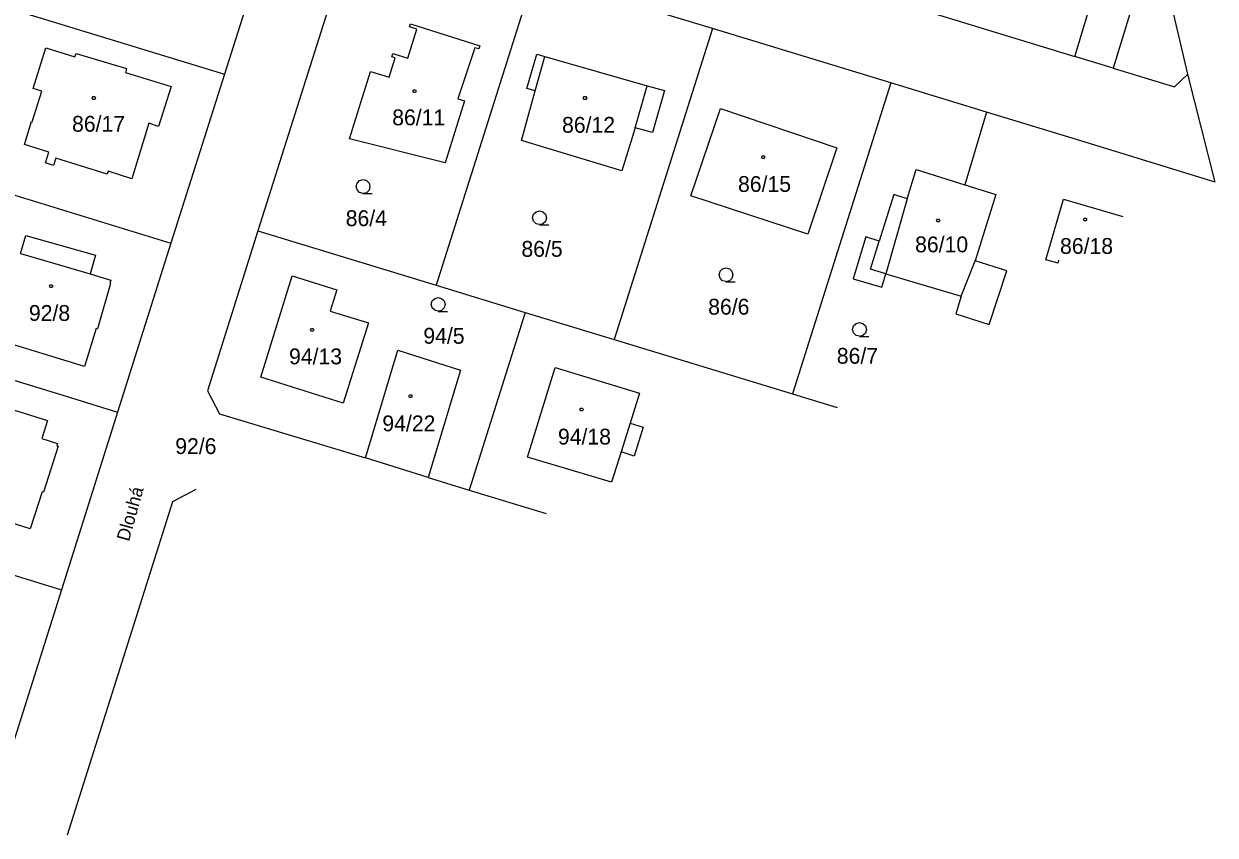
# Model space of a CAD drawing. Extents: x -759060 to -757386, y -1172273 to -1170948.
# Drawn here: x -758007.6 to -757879.8, y -1171577.8 to -1171490.7 of the extents above; entities that cross this region are included whole.
import ezdxf

# ---------------------------------------------------------------- set-up
doc = ezdxf.new("R2010")
doc.units = 0
for name, color, linetype in [('Vrstva 1', 7, 'Continuous'), ('Vrstva 12', 7, 'Continuous'), ('Vrstva 2', 7, 'Continuous'), ('Vrstva 3', 7, 'Continuous'), ('Vrstva 4', 7, 'Continuous'), ('Vrstva 5', 7, 'Continuous'), ('Vrstva 7', 7, 'Continuous')]:
    doc.layers.add(name, color=color, linetype=linetype)

msp = doc.modelspace()

# ---------------------------------------------------------------- linework, layer by layer
at = {"layer": 'Vrstva 1'}
for p, q in [((-757882.7, -1171496.11), (-757887.69, -1171474.68)), ((-757980.65, -1171478.97), (-757986.07, -1171496.14)), ((-757972.53, -1171481.45), (-757982.47, -1171512.93)), ((-757887.51, -1171484.91), (-757890.7, -1171495.49)), ((-758019.54, -1171485.89), (-757986.07, -1171496.14)), ((-757952.81, -1171485.38), (-757963.35, -1171518.77)), ((-757933.7, -1171491.22), (-757952.81, -1171485.38)), ((-757910.62, -1171489.39), (-757894.84, -1171494.23)), ((-757966.4, -1171494.42), (-757965.42, -1171491.31)), ((-757966.21, -1171491.06), (-757966.1, -1171490.73)), ((-757965.42, -1171491.31), (-757966.21, -1171491.06)), ((-757966.1, -1171490.73), (-757958.66, -1171493.08)), ((-757933.7, -1171491.22), (-757944.24, -1171524.61)), ((-757914.58, -1171497.06), (-757933.7, -1171491.22)), ((-758006.58, -1171497.65), (-758005.22, -1171493.31)), ((-758005.22, -1171493.31), (-758002.1, -1171494.28)), ((-758002.1, -1171494.28), (-758001.98, -1171493.9)), ((-758001.98, -1171493.9), (-757996.58, -1171495.53)), ((-757968.1, -1171494.25), (-757968, -1171493.92)), ((-757968, -1171493.92), (-757966.4, -1171494.42)), ((-757959.2, -1171493.28), (-757961.01, -1171498.78)), ((-757958.77, -1171493.41), (-757959.2, -1171493.28)), ((-757958.66, -1171493.08), (-757958.77, -1171493.41)), ((-757953.63, -1171497.65), (-757952.55, -1171493.98)), ((-757952.55, -1171493.98), (-757951.7, -1171494.22)), ((-757968.4, -1171496.45), (-757967.75, -1171494.37)), ((-757967.75, -1171494.37), (-757968.1, -1171494.25)), ((-757951.7, -1171494.22), (-757940.7, -1171497.36)), ((-757890.7, -1171495.49), (-757894.84, -1171494.23)), ((-757996.58, -1171495.53), (-757996.67, -1171495.95)), ((-757996.67, -1171495.95), (-757991.79, -1171497.43)), ((-757986.07, -1171496.14), (-757991.8, -1171514.26)), ((-757972.66, -1171503.06), (-757970.38, -1171495.82)), ((-757970.38, -1171495.82), (-757968.4, -1171496.45)), ((-757890.7, -1171495.49), (-757884.15, -1171497.48)), ((-757884.15, -1171497.48), (-757882.7, -1171496.11)), ((-757879.77, -1171507.7), (-757882.7, -1171496.11)), ((-758005.66, -1171497.93), (-758006.58, -1171497.65)), ((-757991.79, -1171497.43), (-757993.13, -1171501.73)), ((-757952.73, -1171497.91), (-757953.63, -1171497.65)), ((-757940.7, -1171497.36), (-757938.85, -1171497.87)), ((-757914.58, -1171497.06), (-757925.12, -1171530.44)), ((-757904.31, -1171500.2), (-757914.58, -1171497.06)), ((-758006.68, -1171501.25), (-758005.66, -1171497.93)), ((-757960.3, -1171499), (-757962.4, -1171505.65)), ((-757961.01, -1171498.78), (-757960.3, -1171499)), ((-757954.21, -1171503.23), (-757952.73, -1171497.91)), ((-757938.85, -1171497.87), (-757940.14, -1171502.4)), ((-757936.02, -1171509.18), (-757932.86, -1171499.82)), ((-757932.86, -1171499.82), (-757920.37, -1171504.02)), ((-757904.31, -1171500.2), (-757906.64, -1171508)), ((-757895.47, -1171502.9), (-757904.31, -1171500.2)), ((-758007.53, -1171503.67), (-758006.78, -1171501.22)), ((-758006.78, -1171501.22), (-758006.68, -1171501.25)), ((-757994.18, -1171501.38), (-757995.99, -1171507.34)), ((-757993.13, -1171501.73), (-757994.18, -1171501.38)), ((-757942, -1171501.88), (-757943.44, -1171506.49)), ((-757940.14, -1171502.4), (-757942, -1171501.88)), ((-757879.77, -1171507.7), (-757895.47, -1171502.9)), ((-757895.47, -1171502.9), (-757895.47, -1171502.9)), ((-758025.27, -1171504), (-757991.8, -1171514.26)), ((-758004.91, -1171504.5), (-758007.53, -1171503.67)), ((-757962.4, -1171505.65), (-757972.66, -1171503.06)), ((-757943.44, -1171506.49), (-757954.21, -1171503.23)), ((-757920.37, -1171504.02), (-757923.48, -1171513.28)), ((-758005.27, -1171505.65), (-758004.91, -1171504.5)), ((-758004.14, -1171505.13), (-758004.39, -1171505.91)), ((-757998.66, -1171506.87), (-758004.14, -1171505.13)), ((-758004.39, -1171505.91), (-758005.27, -1171505.65)), ((-757998.55, -1171506.52), (-757998.66, -1171506.87)), ((-757995.99, -1171507.34), (-757998.55, -1171506.52)), ((-757912.83, -1171509.49), (-757911.86, -1171506.37)), ((-757911.86, -1171506.37), (-757906.64, -1171508)), ((-757906.64, -1171508), (-757903.3, -1171509.04)), ((-757879.77, -1171507.7), (-757879.77, -1171507.7)), ((-757923.48, -1171513.28), (-757936.02, -1171509.18)), ((-757914.25, -1171509.05), (-757915.81, -1171514.04)), ((-757912.83, -1171509.49), (-757914.25, -1171509.05)), ((-757903.3, -1171509.04), (-757905.52, -1171516.16)), ((-757897.93, -1171516.03), (-757896.06, -1171509.54)), ((-757896.06, -1171509.54), (-757889.67, -1171511.38)), ((-757889.67, -1171511.38), (-757889.67, -1171511.38)), ((-757982.47, -1171512.93), (-757987.89, -1171530.09)), ((-757982.47, -1171512.93), (-757963.35, -1171518.77)), ((-758007.94, -1171515.36), (-758007.36, -1171513.45)), ((-758007.36, -1171513.45), (-757999.9, -1171515.56)), ((-757991.8, -1171514.26), (-757997.52, -1171532.38)), ((-757917.25, -1171513.59), (-757918.6, -1171518.07)), ((-757915.81, -1171514.04), (-757917.25, -1171513.59)), ((-757999.9, -1171515.56), (-758000.48, -1171517.55)), ((-757902.13, -1171517.22), (-757905.52, -1171516.16)), ((-757896.63, -1171516.4), (-757897.93, -1171516.03)), ((-757896.63, -1171516.4), (-757896.54, -1171516.1)), ((-757896.63, -1171516.4), (-757896.63, -1171516.4)), ((-757896.54, -1171516.1), (-757896.54, -1171516.1)), ((-758000.48, -1171517.55), (-757998.26, -1171518.22)), ((-757998.26, -1171518.22), (-757998.37, -1171518.56)), ((-757982.17, -1171528.65), (-757978.79, -1171517.77)), ((-757978.79, -1171517.77), (-757974.01, -1171519.26)), ((-757918.6, -1171518.07), (-757915.55, -1171518.99)), ((-757915.55, -1171518.99), (-757915.12, -1171517.54)), ((-757915.12, -1171517.54), (-757911.24, -1171518.7)), ((-757904.02, -1171523), (-757902.13, -1171517.22)), ((-757998.28, -1171518.59), (-757999.68, -1171523.45)), ((-757998.37, -1171518.56), (-757998.28, -1171518.59)), ((-757974.01, -1171519.26), (-757974.72, -1171521.54)), ((-757963.35, -1171518.77), (-757953.8, -1171521.69)), ((-757911.24, -1171518.7), (-757911.24, -1171518.7)), ((-757911.24, -1171518.7), (-757907.02, -1171519.95)), ((-757907.02, -1171519.95), (-757907.58, -1171521.84)), ((-758030.99, -1171522.11), (-758003.04, -1171530.69)), ((-757974.72, -1171521.54), (-757970.62, -1171522.82)), ((-757953.8, -1171521.69), (-757959.8, -1171540.76)), ((-757953.8, -1171521.69), (-757944.24, -1171524.61)), ((-757907.58, -1171521.84), (-757904.02, -1171523)), ((-757970.62, -1171522.82), (-757973.32, -1171531.42)), ((-758001.07, -1171527.49), (-758010.74, -1171524.52)), ((-757999.83, -1171523.4), (-758001.07, -1171527.49)), ((-757999.68, -1171523.45), (-757999.83, -1171523.4)), ((-757944.24, -1171524.61), (-757925.12, -1171530.44)), ((-757970.94, -1171537.3), (-757967.47, -1171525.74)), ((-757967.47, -1171525.74), (-757960.74, -1171527.89)), ((-757960.74, -1171527.89), (-757964.21, -1171539.39)), ((-757953.55, -1171537.21), (-757950.59, -1171527.59)), ((-757950.59, -1171527.59), (-757941.55, -1171530.37)), ((-757973.32, -1171531.42), (-757982.17, -1171528.65)), ((-758012.95, -1171530.82), (-758005.04, -1171533.3)), ((-758003.04, -1171530.69), (-757997.52, -1171532.38)), ((-757987.89, -1171530.09), (-757986.58, -1171532.58)), ((-757941.55, -1171530.37), (-757942.55, -1171533.56)), ((-757925.12, -1171530.44), (-757920.34, -1171531.9)), ((-757920.34, -1171531.9), (-757920.34, -1171531.9)), ((-757920.34, -1171531.9), (-757920.34, -1171531.9)), ((-758005.04, -1171533.3), (-758005.64, -1171535.21)), ((-757997.52, -1171532.38), (-758003.55, -1171551.46)), ((-757986.58, -1171532.58), (-757970.94, -1171537.3)), ((-757942.55, -1171533.56), (-757941.15, -1171534)), ((-757941.15, -1171534), (-757942.1, -1171537.1)), ((-758005.64, -1171535.21), (-758003.96, -1171535.74)), ((-758003.92, -1171536.05), (-758005.49, -1171540.97)), ((-758003.96, -1171535.74), (-758004.05, -1171536.01)), ((-758004.05, -1171536.01), (-758003.92, -1171536.05)), ((-757964.21, -1171539.39), (-757970.94, -1171537.3)), ((-757944.52, -1171539.89), (-757953.55, -1171537.21)), ((-757943.51, -1171536.65), (-757944.52, -1171539.89)), ((-757942.1, -1171537.1), (-757943.51, -1171536.65)), ((-757964.21, -1171539.39), (-757959.8, -1171540.76)), ((-758005.63, -1171540.93), (-758006.9, -1171544.93)), ((-758005.49, -1171540.97), (-758005.63, -1171540.93)), ((-757989.14, -1171540.69), (-757991.65, -1171542.02)), ((-757989.14, -1171540.69), (-757989.14, -1171540.69)), ((-757959.8, -1171540.76), (-757951.55, -1171543.28)), ((-758006.9, -1171544.93), (-758016.47, -1171541.87)), ((-757991.65, -1171542.02), (-758002.95, -1171577.79)), ((-758028.41, -1171543.82), (-758003.55, -1171551.46)), ((-757951.55, -1171543.28), (-757951.55, -1171543.28)), ((-757951.55, -1171543.28), (-757951.55, -1171543.28)), ((-758003.55, -1171551.46), (-758011.08, -1171575.3)), ((-758002.95, -1171577.79), (-758002.95, -1171577.79))]:
    msp.add_line(p, q, dxfattribs=at)
at = {"layer": 'Vrstva 12'}
for p, q in [((-757887.51, -1171484.91), (-757890.7, -1171495.49)), ((-757894.84, -1171494.23), (-757893.33, -1171489.26)), ((-757966.4, -1171494.42), (-757965.42, -1171491.31)), ((-757966.21, -1171491.06), (-757966.1, -1171490.73)), ((-757965.42, -1171491.31), (-757966.21, -1171491.06)), ((-757966.1, -1171490.73), (-757958.66, -1171493.08)), ((-758006.58, -1171497.65), (-758005.22, -1171493.31)), ((-758005.22, -1171493.31), (-758002.1, -1171494.28)), ((-758002.1, -1171494.28), (-758001.98, -1171493.9)), ((-758001.98, -1171493.9), (-757996.58, -1171495.53)), ((-757968.1, -1171494.25), (-757968, -1171493.92)), ((-757968, -1171493.92), (-757966.4, -1171494.42)), ((-757959.2, -1171493.28), (-757961.01, -1171498.78)), ((-757958.77, -1171493.41), (-757959.2, -1171493.28)), ((-757958.66, -1171493.08), (-757958.77, -1171493.41)), ((-757968.4, -1171496.45), (-757967.75, -1171494.37)), ((-757967.75, -1171494.37), (-757968.1, -1171494.25)), ((-757952.73, -1171497.91), (-757951.7, -1171494.22)), ((-757951.7, -1171494.22), (-757940.7, -1171497.36)), ((-757890.7, -1171495.49), (-757894.84, -1171494.23)), ((-757996.58, -1171495.53), (-757996.67, -1171495.95)), ((-757996.67, -1171495.95), (-757991.79, -1171497.43)), ((-757972.66, -1171503.06), (-757970.38, -1171495.82)), ((-757970.38, -1171495.82), (-757968.4, -1171496.45)), ((-758005.66, -1171497.93), (-758006.58, -1171497.65)), ((-757991.79, -1171497.43), (-757993.13, -1171501.73)), ((-757942, -1171501.88), (-757940.7, -1171497.36)), ((-758006.68, -1171501.25), (-758005.66, -1171497.93)), ((-757960.3, -1171499), (-757962.4, -1171505.65)), ((-757961.01, -1171498.78), (-757960.3, -1171499)), ((-757954.21, -1171503.23), (-757952.73, -1171497.91)), ((-757936.02, -1171509.18), (-757932.86, -1171499.82)), ((-757932.86, -1171499.82), (-757920.37, -1171504.02)), ((-758007.53, -1171503.67), (-758006.78, -1171501.22)), ((-758006.78, -1171501.22), (-758006.68, -1171501.25)), ((-757994.18, -1171501.38), (-757995.99, -1171507.34)), ((-757993.13, -1171501.73), (-757994.18, -1171501.38)), ((-757942, -1171501.88), (-757943.44, -1171506.49)), ((-758004.91, -1171504.5), (-758007.53, -1171503.67)), ((-757962.4, -1171505.65), (-757972.66, -1171503.06)), ((-757943.44, -1171506.49), (-757954.21, -1171503.23)), ((-757920.37, -1171504.02), (-757923.48, -1171513.28)), ((-758005.27, -1171505.65), (-758004.91, -1171504.5)), ((-758004.14, -1171505.13), (-758004.39, -1171505.91)), ((-757998.66, -1171506.87), (-758004.14, -1171505.13)), ((-758004.39, -1171505.91), (-758005.27, -1171505.65)), ((-757998.55, -1171506.52), (-757998.66, -1171506.87)), ((-757995.99, -1171507.34), (-757998.55, -1171506.52)), ((-757912.83, -1171509.49), (-757911.86, -1171506.37)), ((-757911.86, -1171506.37), (-757906.64, -1171508)), ((-757906.64, -1171508), (-757903.3, -1171509.04)), ((-757923.48, -1171513.28), (-757936.02, -1171509.18)), ((-757903.3, -1171509.04), (-757905.52, -1171516.16)), ((-757912.83, -1171509.49), (-757915.12, -1171517.54)), ((-757897.93, -1171516.03), (-757896.06, -1171509.54)), ((-757896.06, -1171509.54), (-757889.67, -1171511.38)), ((-757889.67, -1171511.38), (-757889.67, -1171511.38)), ((-758007.94, -1171515.36), (-758000.48, -1171517.55)), ((-757907.02, -1171519.95), (-757905.52, -1171516.16)), ((-757896.63, -1171516.4), (-757897.93, -1171516.03)), ((-757896.63, -1171516.4), (-757896.54, -1171516.1)), ((-757896.63, -1171516.4), (-757896.54, -1171516.1)), ((-757896.63, -1171516.4), (-757896.63, -1171516.4)), ((-757896.54, -1171516.1), (-757896.54, -1171516.1)), ((-757896.54, -1171516.1), (-757896.54, -1171516.1)), ((-758000.48, -1171517.55), (-757998.26, -1171518.22)), ((-757998.26, -1171518.22), (-757998.37, -1171518.56)), ((-757982.17, -1171528.65), (-757978.79, -1171517.77)), ((-757978.79, -1171517.77), (-757974.01, -1171519.26)), ((-757915.12, -1171517.54), (-757911.24, -1171518.7)), ((-757998.28, -1171518.59), (-757999.68, -1171523.45)), ((-757998.37, -1171518.56), (-757998.28, -1171518.59)), ((-757974.01, -1171519.26), (-757974.72, -1171521.54)), ((-757911.24, -1171518.7), (-757907.02, -1171519.95)), ((-757974.72, -1171521.54), (-757970.62, -1171522.82)), ((-757970.62, -1171522.82), (-757973.32, -1171531.42)), ((-758001.07, -1171527.49), (-758010.74, -1171524.52)), ((-757999.83, -1171523.4), (-758001.07, -1171527.49)), ((-757999.68, -1171523.45), (-757999.83, -1171523.4)), ((-757970.94, -1171537.3), (-757967.47, -1171525.74)), ((-757967.47, -1171525.74), (-757960.74, -1171527.89)), ((-757960.74, -1171527.89), (-757964.21, -1171539.39)), ((-757953.55, -1171537.21), (-757950.59, -1171527.59)), ((-757950.59, -1171527.59), (-757941.55, -1171530.37)), ((-757973.32, -1171531.42), (-757982.17, -1171528.65)), ((-758012.95, -1171530.82), (-758005.04, -1171533.3)), ((-757941.55, -1171530.37), (-757942.55, -1171533.56)), ((-758005.04, -1171533.3), (-758005.64, -1171535.21)), ((-757942.55, -1171533.56), (-757943.51, -1171536.65)), ((-758005.64, -1171535.21), (-758003.96, -1171535.74)), ((-758003.92, -1171536.05), (-758005.49, -1171540.97)), ((-758003.96, -1171535.74), (-758004.05, -1171536.01)), ((-758004.05, -1171536.01), (-758003.92, -1171536.05)), ((-757964.21, -1171539.39), (-757970.94, -1171537.3)), ((-757944.52, -1171539.89), (-757953.55, -1171537.21)), ((-757943.51, -1171536.65), (-757944.52, -1171539.89)), ((-758005.63, -1171540.93), (-758006.9, -1171544.93)), ((-758005.49, -1171540.97), (-758005.63, -1171540.93)), ((-758006.9, -1171544.93), (-758016.47, -1171541.87))]:
    msp.add_line(p, q, dxfattribs=at)
at = {"layer": 'Vrstva 3'}
for points in [[(-757971.18, -1171508.92), (-757971.56, -1171508.82), (-757971.83, -1171508.55), (-757971.93, -1171508.18), (-757971.83, -1171507.81), (-757971.56, -1171507.54), (-757971.19, -1171507.44), (-757970.82, -1171507.54), (-757970.55, -1171507.81), (-757970.45, -1171508.19), (-757970.55, -1171508.57), (-757970.82, -1171508.84), (-757971.2, -1171508.94), (-757970.2, -1171508.94)], [(-757952.25, -1171512.27), (-757952.63, -1171512.17), (-757952.9, -1171511.9), (-757953, -1171511.53), (-757952.9, -1171511.16), (-757952.63, -1171510.89), (-757952.26, -1171510.79), (-757951.89, -1171510.89), (-757951.62, -1171511.16), (-757951.52, -1171511.54), (-757951.62, -1171511.92), (-757951.89, -1171512.19), (-757952.27, -1171512.29), (-757951.27, -1171512.29)], [(-757932.24, -1171518.39), (-757932.62, -1171518.29), (-757932.89, -1171518.02), (-757932.99, -1171517.65), (-757932.89, -1171517.28), (-757932.62, -1171517.01), (-757932.25, -1171516.91), (-757931.88, -1171517.01), (-757931.61, -1171517.28), (-757931.51, -1171517.66), (-757931.61, -1171518.04), (-757931.88, -1171518.31), (-757932.26, -1171518.41), (-757931.26, -1171518.41)], [(-757963.12, -1171521.56), (-757963.5, -1171521.46), (-757963.77, -1171521.19), (-757963.87, -1171520.82), (-757963.77, -1171520.45), (-757963.5, -1171520.18), (-757963.13, -1171520.08), (-757962.76, -1171520.18), (-757962.49, -1171520.45), (-757962.39, -1171520.83), (-757962.49, -1171521.21), (-757962.76, -1171521.48), (-757963.14, -1171521.58), (-757962.14, -1171521.58)], [(-757917.92, -1171524.25), (-757918.3, -1171524.15), (-757918.57, -1171523.88), (-757918.67, -1171523.51), (-757918.57, -1171523.14), (-757918.3, -1171522.87), (-757917.93, -1171522.77), (-757917.56, -1171522.87), (-757917.29, -1171523.14), (-757917.19, -1171523.52), (-757917.29, -1171523.9), (-757917.56, -1171524.17), (-757917.94, -1171524.27), (-757916.94, -1171524.27)]]:
    msp.add_lwpolyline(points, dxfattribs=at)
at = {"layer": 'Vrstva 4'}
for p, q in [((-757894.84, -1171494.23), (-757893.33, -1171489.26)), ((-757952.73, -1171497.91), (-757951.7, -1171494.22)), ((-757942, -1171501.88), (-757940.7, -1171497.36)), ((-757912.83, -1171509.49), (-757915.12, -1171517.54)), ((-757916.76, -1171517.06), (-757915.81, -1171514.04)), ((-758007.94, -1171515.36), (-758000.48, -1171517.55)), ((-757907.02, -1171519.95), (-757905.52, -1171516.16)), ((-757915.12, -1171517.54), (-757916.76, -1171517.06)), ((-757942.55, -1171533.56), (-757943.51, -1171536.65))]:
    msp.add_line(p, q, dxfattribs=at)
at = {"layer": 'Vrstva 5'}
for points in [[(-757965.58, -1171497.79), (-757965.49, -1171497.94), (-757965.58, -1171498.09), (-757965.76, -1171498.09), (-757965.85, -1171497.94), (-757965.76, -1171497.79)], [(-757999.97, -1171498.53), (-757999.88, -1171498.68), (-757999.97, -1171498.83), (-758000.15, -1171498.83), (-758000.24, -1171498.68), (-758000.15, -1171498.53)], [(-757947.29, -1171498.53), (-757947.2, -1171498.68), (-757947.29, -1171498.83), (-757947.47, -1171498.83), (-757947.56, -1171498.68), (-757947.47, -1171498.53)], [(-757928.19, -1171504.88), (-757928.1, -1171505.03), (-757928.19, -1171505.18), (-757928.37, -1171505.18), (-757928.46, -1171505.03), (-757928.37, -1171504.88)], [(-757909.39, -1171511.68), (-757909.3, -1171511.83), (-757909.39, -1171511.98), (-757909.57, -1171511.98), (-757909.66, -1171511.83), (-757909.57, -1171511.68)], [(-757893.64, -1171511.57), (-757893.55, -1171511.72), (-757893.64, -1171511.87), (-757893.82, -1171511.87), (-757893.91, -1171511.72), (-757893.82, -1171511.57)], [(-758004.56, -1171518.73), (-758004.47, -1171518.88), (-758004.56, -1171519.03), (-758004.74, -1171519.03), (-758004.83, -1171518.88), (-758004.74, -1171518.73)], [(-757976.56, -1171523.4), (-757976.47, -1171523.55), (-757976.56, -1171523.7), (-757976.74, -1171523.7), (-757976.83, -1171523.55), (-757976.74, -1171523.4)], [(-757966.02, -1171530.53), (-757965.93, -1171530.68), (-757966.02, -1171530.83), (-757966.2, -1171530.83), (-757966.29, -1171530.68), (-757966.2, -1171530.53)], [(-757947.65, -1171531.96), (-757947.56, -1171532.11), (-757947.65, -1171532.26), (-757947.83, -1171532.26), (-757947.92, -1171532.11), (-757947.83, -1171531.96)]]:
    msp.add_lwpolyline(points, close=True, dxfattribs=at)

# ---------------------------------------------------------------- texts
at = {"layer": 'Vrstva 2'}
for s, p in [('86/11', (-757968.063, -1171501.61)), ('86/17', (-758002.413, -1171502.3)), ('86/12', (-757949.843, -1171502.41)), ('86/15', (-757930.963, -1171508.76)), ('86/4', (-757973.053, -1171512.43)), ('86/5', (-757954.203, -1171515.72)), ('86/10', (-757911.963, -1171515.24)), ('86/18', (-757896.413, -1171515.41)), ('92/8', (-758007.043, -1171522.6)), ('86/6', (-757934.163, -1171521.93)), ('94/5', (-757964.723, -1171525.05)), ('94/13', (-757979.133, -1171527.26)), ('86/7', (-757920.363, -1171527.2)), ('94/22', (-757969.123, -1171534.45)), ('94/18', (-757950.283, -1171535.87)), ('92/6', (-757991.343, -1171536.89))]:
    msp.add_text(s, height=1.7, dxfattribs=at).set_placement(p)
at = {"layer": 'Vrstva 7'}
msp.add_text('Dlouhá', height=1.4, rotation=74.48451, dxfattribs=at).set_placement((-757996.305, -1171546.336))

doc.saveas('drawing.dxf')
